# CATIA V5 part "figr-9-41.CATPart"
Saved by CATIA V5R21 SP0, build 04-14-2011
Part number: Part1
Bounding box of the stored display mesh (mm): x -40 to 40, y -20.616 to 191.034, z 0 to 131.022
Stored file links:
  D:\CATIA V5R21 E-RESOURCES\CATIA-V5R21\catia-v5r21-prt\c09-catia-v5r20-prt\c09-catia-v5r21-figr-9-41.CATPart
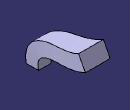
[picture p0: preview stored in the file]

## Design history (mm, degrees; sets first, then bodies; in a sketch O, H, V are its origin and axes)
Set1
  Plane1: type Normal, Curve Sketch2, RefPoint vertex of Sketch2
Body1 (main body)
  Sketch1 on xy-plane, origin (0, 0, 0), H (1, 0, 0), V (0, 1, 0)
    line L1 (20, 20) -> (20, -20)
    line L2 (20, -20) -> (-20, -20)
    line L3 (-20, -20) -> (-20, 20)
    line L4 (-20, 20) -> (20, 20)
    vertical: L1 V, L3 V
    horizontal: L2 H, L4 H
    equidistance: L1 L3 O, L2 L4 O
  Sketch2 on yz-plane, origin (0, 0, 0), H (0, 1, 0), V (0, 0, 1)
    spline S1 through (0, 0) (20, 60) (60, 80) (120, 90) (180, 110)
    point P1 (0, 0)
    coincidence: P1 O
  Sketch3 on Plane1, origin (0, 186.3865, 97.8327), H (1, 0, 0), V (0, -0.4648, 0.8854)
    point P1 (0, 13.7415)
    line L1 (40, 37.4831) -> (40, -10)
    line L2 (40, -10) -> (-40, -10)
    line L3 (-40, -10) -> (-40, 37.4831)
    line L4 (-40, 37.4831) -> (40, 37.4831)
    reference projected point E1 (0, 13.7415) from vertex of Sketch2
    coincidence: P1 V, P1 E1
    vertical: L1 V, L3 V
    horizontal: L2 H, L4 H
    equidistance: L1 L3 P1, L2 L4 P1
  Loft1: Sections (Sketch1; Sketch3), Spine Sketch2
